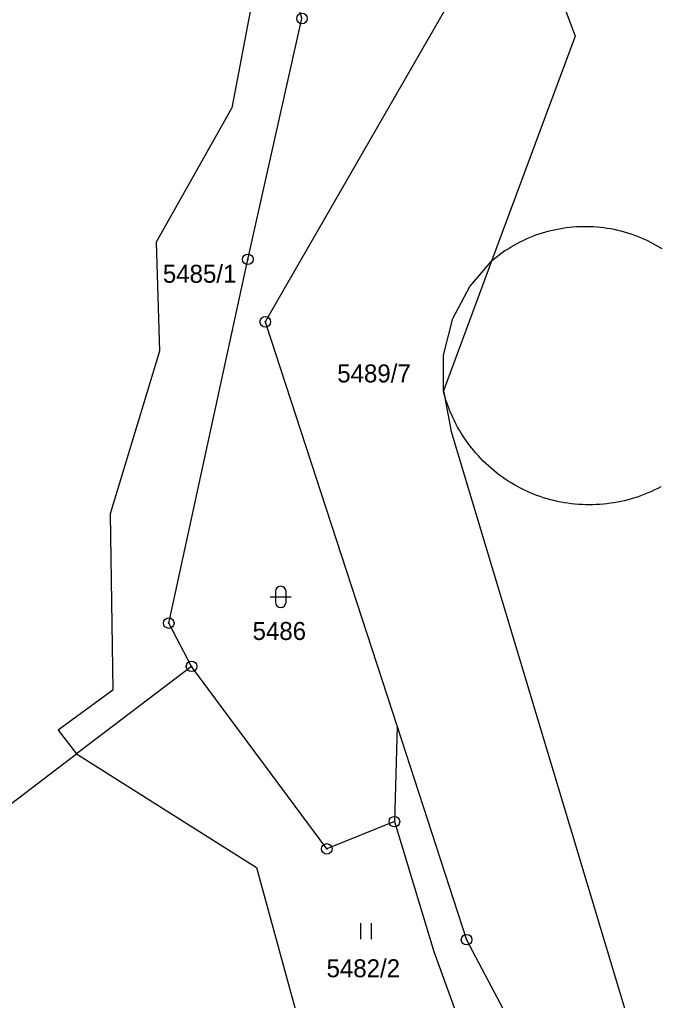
# Model space of a CAD drawing. Extents: x -644096 to -634268, y -1141430 to -1133463.
# Drawn here: x -638321.8 to -638261.3, y -1139945.5 to -1139852.7 of the extents above; entities that cross this region are included whole.
import ezdxf

# ---------------------------------------------------------------- set-up
doc = ezdxf.new("R2010")
doc.units = 0
for name, color, linetype in [('_CIVIL_CONSTRUCTION', 7, 'Continuous'), ('M_Svah_Nasyp', 7, 'Continuous'), ('svrsek_osa_sjezdy', 7, 'Continuous'), ('svrsek_osa_VRT', 7, 'Continuous'), ('terminal_VRT', 7, 'Continuous')]:
    doc.layers.add(name, color=color, linetype=linetype)

msp = doc.modelspace()

# ---------------------------------------------------------------- linework, layer by layer
at = {"layer": '_CIVIL_CONSTRUCTION'}
for centre, radius in [((-638295.06, -1139852.64), 0.5), ((-638300.18, -1139875.41), 0.5), ((-638300.18, -1139875.41), 0.0303), ((-638298.53, -1139881.32), 0.5), ((-638298.53, -1139881.32), 0.0303), ((-638307.66, -1139909.8), 0.5), ((-638307.66, -1139909.8), 0.0303), ((-638305.5, -1139913.89), 0.5), ((-638305.5, -1139913.89), 0.0303), ((-638286.32, -1139928.57), 0.5), ((-638286.32, -1139928.57), 0.0303), ((-638292.71, -1139931.15), 0.5), ((-638292.71, -1139931.15), 0.0303), ((-638279.49, -1139939.73), 0.5), ((-638279.49, -1139939.73), 0.0303)]:
    msp.add_circle(centre, radius, dxfattribs=at)
at = {"layer": 'M_Svah_Nasyp'}
for p, q in [((-638275.83, -1139874.58), (-638277.14, -1139875.58)), ((-638279.2, -1139877.97), (-638277.14, -1139875.58)), ((-638280.8, -1139881), (-638279.2, -1139877.97)), ((-638281.67, -1139884.48), (-638280.8, -1139881)), ((-638281.69, -1139887.83), (-638281.67, -1139884.48))]:
    msp.add_line(p, q, dxfattribs=at)
for points in [[(-638275.83, -1139874.58), (-638275.557, -1139874.402), (-638275.28, -1139874.23), (-638274.998, -1139874.066), (-638274.713, -1139873.908), (-638274.424, -1139873.757), (-638274.132, -1139873.613), (-638273.836, -1139873.476), (-638273.537, -1139873.346), (-638273.235, -1139873.223), (-638272.93, -1139873.108), (-638272.622, -1139873), (-638272.312, -1139872.9), (-638271.999, -1139872.807), (-638271.685, -1139872.721), (-638271.368, -1139872.644), (-638271.05, -1139872.573), (-638270.73, -1139872.511), (-638270.408, -1139872.456), (-638270.086, -1139872.409), (-638269.762, -1139872.37), (-638269.438, -1139872.338), (-638269.112, -1139872.315), (-638268.787, -1139872.299), (-638268.461, -1139872.291), (-638268.135, -1139872.291), (-638267.809, -1139872.298), (-638267.483, -1139872.314), (-638267.158, -1139872.337), (-638266.833, -1139872.368), (-638266.51, -1139872.407), (-638266.187, -1139872.454), (-638265.866, -1139872.509), (-638265.546, -1139872.571), (-638265.227, -1139872.641), (-638264.911, -1139872.718), (-638264.596, -1139872.803), (-638264.283, -1139872.896), (-638263.973, -1139872.996), (-638263.665, -1139873.104), (-638263.36, -1139873.219), (-638263.058, -1139873.341), (-638262.759, -1139873.47), (-638262.463, -1139873.607), (-638262.17, -1139873.751), (-638261.881, -1139873.902), (-638261.596, -1139874.059), (-638261.314, -1139874.224), (-638261.037, -1139874.395)], [(-638261.116, -1139896.907), (-638261.414, -1139897.063), (-638261.716, -1139897.213), (-638262.021, -1139897.355), (-638262.33, -1139897.49), (-638262.641, -1139897.618), (-638262.956, -1139897.738), (-638263.273, -1139897.851), (-638263.593, -1139897.956), (-638263.915, -1139898.054), (-638264.239, -1139898.144), (-638264.566, -1139898.226), (-638264.894, -1139898.301), (-638265.224, -1139898.367), (-638265.556, -1139898.426), (-638265.889, -1139898.477), (-638266.222, -1139898.521), (-638266.557, -1139898.556), (-638266.893, -1139898.583), (-638267.229, -1139898.603), (-638267.566, -1139898.614), (-638267.902, -1139898.618), (-638268.239, -1139898.613), (-638268.575, -1139898.601), (-638268.911, -1139898.58), (-638269.247, -1139898.552), (-638269.582, -1139898.516), (-638269.916, -1139898.472), (-638270.248, -1139898.42), (-638270.58, -1139898.36), (-638270.909, -1139898.292), (-638271.237, -1139898.216), (-638271.564, -1139898.133), (-638271.888, -1139898.042), (-638272.21, -1139897.944), (-638272.529, -1139897.837), (-638272.846, -1139897.724), (-638273.16, -1139897.603), (-638273.472, -1139897.474), (-638273.78, -1139897.338), (-638274.084, -1139897.195), (-638274.386, -1139897.045), (-638274.683, -1139896.887), (-638274.977, -1139896.723), (-638275.267, -1139896.551), (-638275.553, -1139896.373), (-638275.834, -1139896.189), (-638276.111, -1139895.997), (-638276.384, -1139895.799), (-638276.651, -1139895.595), (-638276.914, -1139895.384), (-638277.172, -1139895.167), (-638277.424, -1139894.945), (-638277.671, -1139894.716), (-638277.913, -1139894.481), (-638278.149, -1139894.241), (-638278.379, -1139893.996), (-638278.603, -1139893.745), (-638278.822, -1139893.488), (-638279.034, -1139893.227), (-638279.24, -1139892.961), (-638279.44, -1139892.69), (-638279.633, -1139892.414), (-638279.82, -1139892.134), (-638279.999, -1139891.849), (-638280.173, -1139891.56), (-638280.339, -1139891.267), (-638280.498, -1139890.971), (-638280.65, -1139890.67), (-638280.796, -1139890.367), (-638280.933, -1139890.059), (-638281.064, -1139889.749), (-638281.187, -1139889.436), (-638281.303, -1139889.119), (-638281.411, -1139888.801), (-638281.512, -1139888.479), (-638281.605, -1139888.156), (-638281.69, -1139887.83)]]:
    msp.add_lwpolyline(points, dxfattribs=at)
at = {"layer": 'svrsek_osa_sjezdy'}
for p, q in [((-638298.071, -1139907.321), (-638296.069, -1139907.321)), ((-638297.571, -1139906.821), (-638297.571, -1139907.822)), ((-638296.569, -1139907.822), (-638296.569, -1139906.821)), ((-638289.501, -1139939.67), (-638289.501, -1139938.17)), ((-638288.5, -1139939.67), (-638288.5, -1139938.17))]:
    msp.add_line(p, q, dxfattribs=at)
for centre, start, end in [((-638297.07, -1139906.821), 0, 180), ((-638297.07, -1139907.821), 180, 359.98789)]:
    msp.add_arc(centre, 0.5, start, end, dxfattribs=at)
at = {"layer": 'terminal_VRT'}
for p, q in [((-638305.5, -1139913.89), (-638316.38, -1139922.17)), ((-638286.06, -1139919.57), (-638286.32, -1139928.57))]:
    msp.add_line(p, q, dxfattribs=at)
for points in [[(-638308.17, -1139741.94), (-638299.87, -1139780.51), (-638279.07, -1139827.95), (-638269.23, -1139854.31), (-638277.14, -1139875.58), (-638281.69, -1139887.83), (-638280.96, -1139891.67), (-638260.12, -1139960.99), (-638250.7, -1139982.63)], [(-638305.5, -1139913.89), (-638307.66, -1139909.8), (-638300.18, -1139875.41), (-638295.06, -1139852.64), (-638299.26, -1139836.91), (-638309, -1139821.43)], [(-638317.88, -1139825.5), (-638316.71, -1139826.99), (-638303.2, -1139839.31), (-638299.72, -1139850.61), (-638301.7, -1139861.08), (-638308.86, -1139873.77)], [(-638279.83, -1139848.79), (-638298.53, -1139881.32), (-638286.06, -1139919.57)], [(-638308.86, -1139873.77), (-638308.52, -1139884.08), (-638313.21, -1139899.47), (-638312.96, -1139916.14), (-638318.11, -1139919.91), (-638316.38, -1139922.17)], [(-638286.32, -1139928.57), (-638292.71, -1139931.15), (-638305.5, -1139913.89)], [(-638286.06, -1139919.57), (-638279.49, -1139939.73), (-638262.27, -1139972.32)], [(-638374.5, -1139973.29), (-638334.75, -1139936.15), (-638316.38, -1139922.17)], [(-638316.38, -1139922.17), (-638299.35, -1139932.92), (-638292.76, -1139956.99), (-638299.77, -1139962.76), (-638298.4, -1139965.33)], [(-638286.32, -1139928.57), (-638282.58, -1139940.86), (-638280.14, -1139947.63)]]:
    msp.add_lwpolyline(points, dxfattribs=at)

# ---------------------------------------------------------------- texts
at = {"layer": 'svrsek_osa_VRT'}
for s, p in [('5485/1', (-638308.216, -1139877.625)), ('5489/7', (-638291.726, -1139887.045)), ('5486', (-638299.731, -1139911.395)), ('5482/2', (-638292.736, -1139943.285))]:
    msp.add_text(s, height=1.7, dxfattribs=at).set_placement(p)

doc.saveas('drawing.dxf')
